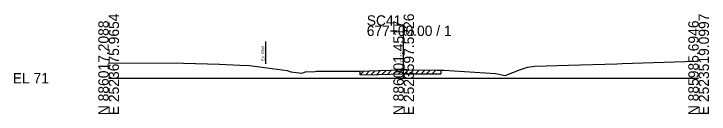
# Model space of a CAD drawing. Extents: x -26 to 183, y -10 to 24021.
# Drawn here: x -25.7 to 162.8, y 9490.3 to 9517.4 of the extents above; entities that cross this region are included whole.
import ezdxf

# ---------------------------------------------------------------- set-up
doc = ezdxf.new("R2010")
doc.units = 0
for name, color, linetype in [('RD_GPK_XS_Cell', 7, 'Continuous'), ('RD_XS_ExGround', 7, 'Continuous'), ('RD_XS_ExPaveRet', 7, 'Continuous'), ('RD_XS_ExRW', 7, 'Continuous'), ('RD_XS_TX_Elev_EX', 7, 'Continuous')]:
    doc.layers.add(name, color=color, linetype=linetype)

msp = doc.modelspace()

# ---------------------------------------------------------------- linework, layer by layer
at = {"layer": 'RD_GPK_XS_Cell'}
for p, q in [((80, 9500), (80, 9514.21)), ((0, 9500), (80, 9500)), ((80, 9500), (160, 9500))]:
    msp.add_line(p, q, dxfattribs=at)
at = {"layer": 'RD_XS_ExGround'}
for p, q in [((0, 9504.19), (20.29, 9504.1)), ((20.29, 9504.1), (30.1, 9503.83)), ((137.86, 9503.85), (139.22, 9503.98)), ((139.22, 9503.98), (159.18, 9504.63)), ((159.18, 9504.63), (160, 9504.74)), ((30.1, 9503.83), (35.62, 9503.52)), ((35.62, 9503.52), (38.16, 9503.43)), ((38.16, 9503.43), (44.36, 9502.66)), ((44.36, 9502.66), (48.44, 9502.1)), ((48.44, 9502.1), (49.44, 9501.7)), ((73.15, 9502.04), (79.56, 9502.22)), ((79.56, 9502.22), (80, 9502.22)), ((80, 9502.22), (89.05, 9502.2)), ((89.05, 9502.2), (90.13, 9502.2)), ((90.13, 9502.2), (90.92, 9502.16)), ((90.92, 9502.16), (104.87, 9501.28)), ((107.55, 9500.69), (111.69, 9502.38)), ((111.69, 9502.38), (113.62, 9503.02)), ((113.62, 9503.02), (115.58, 9503.22)), ((115.58, 9503.22), (124.67, 9503.5)), ((124.67, 9503.5), (137.86, 9503.85)), ((49.44, 9501.7), (52.41, 9501.37)), ((52.41, 9501.37), (53.4, 9501.71)), ((53.4, 9501.71), (55.97, 9501.8)), ((55.97, 9501.8), (56.37, 9501.87)), ((56.37, 9501.87), (68.21, 9501.89)), ((68.21, 9501.89), (73.15, 9502.04)), ((104.87, 9501.28), (107.55, 9500.69))]:
    msp.add_line(p, q, dxfattribs=at)
at = {"layer": 'RD_XS_ExPaveRet'}
for p, q in [((72.71, 9501.03), (73.74, 9502.06)), ((74.21, 9501.07), (75.24, 9502.1)), ((75.71, 9501.11), (76.74, 9502.14)), ((77.21, 9501.15), (78.24, 9502.18)), ((78.71, 9501.19), (79.73, 9502.22)), ((80.21, 9501.22), (81.21, 9502.21)), ((81.71, 9501.21), (82.71, 9502.21)), ((83.21, 9501.21), (84.21, 9502.21)), ((84.71, 9501.21), (85.71, 9502.21)), ((86.21, 9501.21), (87.21, 9502.21)), ((87.71, 9501.2), (88.71, 9502.2)), ((90.13, 9502.2), (90.13, 9501.2)), ((68.21, 9500.89), (69.24, 9501.92)), ((68.21, 9500.89), (68.21, 9501.89)), ((68.21, 9500.89), (73.15, 9501.04)), ((69.71, 9500.94), (70.74, 9501.97)), ((71.21, 9500.98), (72.24, 9502.01)), ((73.15, 9501.04), (79.56, 9501.22)), ((79.56, 9501.22), (80, 9501.22)), ((80, 9501.22), (89.05, 9501.2)), ((89.05, 9501.2), (90.13, 9501.2))]:
    msp.add_line(p, q, dxfattribs=at)
at = {"layer": 'RD_XS_ExRW'}
msp.add_line((42.5, 9509.89), (42.5, 9503.89), dxfattribs=at)

# ---------------------------------------------------------------- texts
at = {"layer": 'RD_GPK_XS_Cell'}
for s, p in [('E 2523675.9654', (2.8, 9490)), ('E 2523597.5326', (82.8, 9490)), ('E 2523519.0997', (162.8, 9490)), ('N 886017.2088', (0, 9490)), ('N 886001.4517', (80, 9490)), ('N 885985.6946', (160, 9490))]:
    msp.add_text(s, height=2.8, rotation=90, dxfattribs=at).set_placement(p)
for s, p in [('SC41', (70, 9514.21)), ('677+00.00 / 1', (70, 9511.41)), ('EL 71', (-26, 9498.6))]:
    msp.add_text(s, height=2.8, dxfattribs=at).set_placement(p)
at = {"layer": 'RD_XS_ExRW'}
msp.add_text('Ex. R/W ', height=0.8, rotation=90, dxfattribs=at).set_placement((42.25, 9504.67))
at = {"layer": 'RD_XS_TX_Elev_EX'}
msp.add_text('73.22', height=0.8, rotation=90, dxfattribs=at).set_placement((79.9, 9504.22))

doc.saveas('drawing.dxf')
